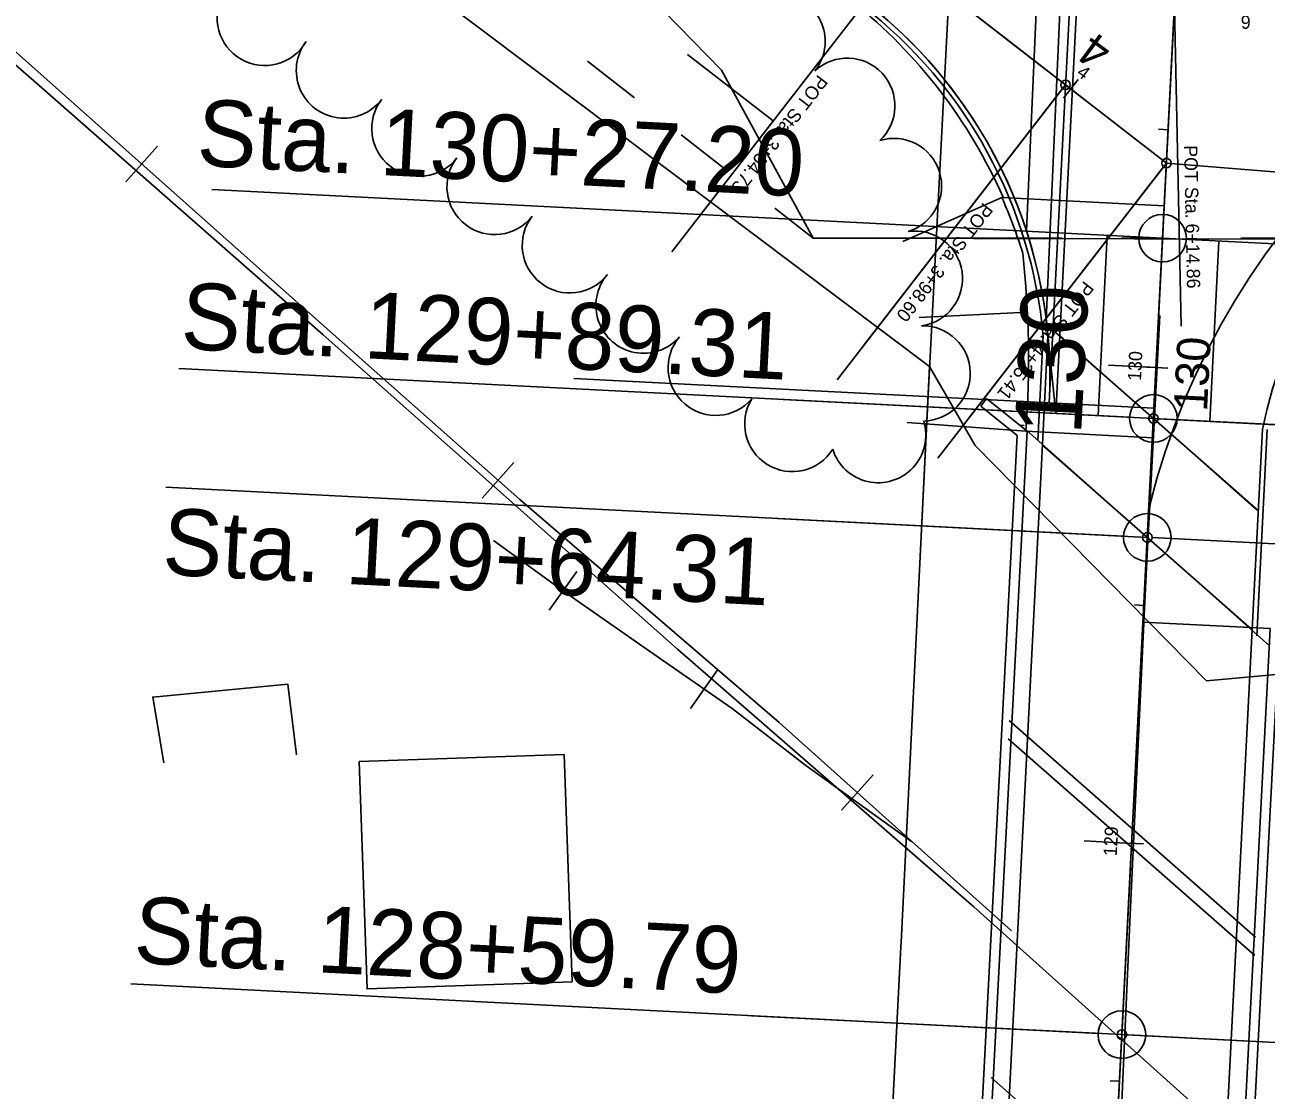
# Model space of a CAD drawing. Extents: x -25029 to 2274964, y -81170 to 687028.
# Drawn here: x -4248.3 to -3987.6, y -66880.9 to -66657.3 of the extents above; entities that cross this region are included whole.
import ezdxf

# ---------------------------------------------------------------- set-up
doc = ezdxf.new("R2010")
doc.units = 0
for name, color, linetype in [('81911BEA - RW_X_Fee_RW', 7, 'Continuous'), ('AP_X_Lights', 7, 'Continuous'), ('AP_X_Runway', 7, 'Continuous'), ('BD_X_Canopy', 7, 'Continuous'), ('BLDG', 7, 'Continuous'), ('BR_X_Rail_Object', 7, 'Continuous'), ('Default', 7, 'Continuous'), ('DIVISIONS', 7, 'Continuous'), ('DV_X_Corp_Line', 7, 'Continuous'), ('GE_X_CL_100', 7, 'Continuous'), ('GE_X_CL_20', 7, 'Continuous'), ('GE_X_CL_2000', 7, 'Continuous'), ('GK_Visualization', 7, 'Continuous'), ('MT_P_Lane_Line', 7, 'Continuous'), ('PM_P_CL_Double_Solid', 7, 'Continuous'), ('PM_P_Yield_Line', 7, 'Continuous'), ('PV_X_Curb', 7, 'Continuous'), ('PV_X_EOP', 7, 'Continuous'), ('RD_P_Gate', 7, 'Continuous'), ('RD_X_GR_Rt', 7, 'Continuous'), ('RD_X_RR_1', 7, 'Continuous'), ('RR', 7, 'Continuous'), ('TREES', 7, 'Continuous'), ('WALL', 7, 'Continuous')]:
    doc.layers.add(name, color=color, linetype=linetype)

msp = doc.modelspace()

# ---------------------------------------------------------------- linework, layer by layer
at = {"layer": '81911BEA - RW_X_Fee_RW'}
msp.add_line((-4044.67, -66469.26), (-4058.6, -66734.98), dxfattribs=at)
for points in [[(-4058.6, -66734.98), (-4060.47, -66773.14), (-4064.24, -66849.91), (-4064.29, -66850.79)], [(-4064.24, -66849.91), (-4064.29, -66850.79), (-4067.04, -66904.37), (-4080.46, -67165.32), (-4085.55, -67264.33), (-4100.93, -67563.4)]]:
    msp.add_lwpolyline(points, dxfattribs=at)
at = {"layer": 'AP_X_Lights'}
msp.add_line((-4009.95, -66718.26), (-4012.05, -66758.11), dxfattribs=at)
at = {"layer": 'AP_X_Runway'}
for p, q in [((-4031.74, -66738.84), (-4018.28, -66475.3)), ((-4009.34, -66702.04), (-3809.48, -66712.25)), ((-4033.42, -66722.48), (-4031.74, -66738.84)), ((-4011.27, -66739.88), (-3810.76, -66750.13)), ((-4017.88, -66869.24), (-3811.75, -66879.76))]:
    msp.add_line(p, q, dxfattribs=at)
msp.add_arc((-4133.02, -66731.48), 100, 5.1647, 52.2156, dxfattribs=at)
at = {"layer": 'BD_X_Canopy'}
for p, q in [((-4033.13, -66736.6), (-4009.6, -66275.87)), ((-4053.51, -67566.81), (-3994.85, -66418.3)), ((-4064.39, -66642.97), (-4112.39, -66704.89)), ((-4091.1, -66677.43), (-4109.14, -66663.45)), ((-4029.72, -66669.84), (-4077.72, -66731.77)), ((-4008.53, -66686.27), (-4056.53, -66748.19)), ((-4011.16, -66737.73), (-4133, -66731.5)), ((-4011.27, -66739.88), (-4089.04, -66735.91)), ((-4012.55, -66764.85), (-4090.32, -66760.88)), ((-4017.88, -66869.24), (-4095.65, -66865.26))]:
    msp.add_line(p, q, dxfattribs=at)
msp.add_arc((-4133, -66731.5), 100, 357.076, 52.2224, dxfattribs=at)
at = {"layer": 'BLDG'}
msp.add_lwpolyline([(-4135.03, -66810.42), (-4133.37, -66858.15), (-4176.4, -66859.64), (-4178.06, -66811.92)], close=True, dxfattribs=at)
at = {"layer": 'BR_X_Rail_Object'}
for p, q in [((-4047.54, -66737.29), (-4046.29, -66735.73)), ((-4039.85, -66743.49), (-4047.54, -66737.29)), ((-4037.8, -66742.57), (-4046.29, -66735.73)), ((-4048.44, -66946.28), (-4037.8, -66742.57)), ((-4037.8, -66742.47), (-3986.92, -66787.57)), ((-4050.34, -66944.22), (-4039.85, -66743.49)), ((-3986.73, -66784.01), (-3997.37, -66988.52)), ((-3984.84, -66786.07), (-3995.05, -66982.32))]:
    msp.add_line(p, q, dxfattribs=at)
at = {"layer": 'Default'}
for p, q in [((-4053.51, -67566.81), (-3987.63, -66276.99)), ((-4384.29, -66395.03), (-4008.53, -66686.26)), ((-4344.77, -66425.66), (-4008.53, -66686.26)), ((-4027.08, -66668.72), (-4030.15, -66672.68)), ((-4028.61, -66670.7), (-4028.61, -66670.7)), ((-4008.53, -66686.26), (-4008.53, -66686.26)), ((-4008.53, -66686.26), (-3651.55, -66715.33)), ((-4033.64, -66720.22), (-3989.23, -66759.26)), ((-4013.22, -66729.07), (-4008.23, -66729.32)), ((-4010.73, -66729.21), (-4010.73, -66729.21)), ((-4038.38, -66741.38), (-4039.38, -66741.32)), ((-4034.59, -66745.48), (-3990.51, -66784.23)), ((-4041.55, -66803.3), (-3989.8, -66848.79)), ((-4041.74, -66807.13), (-3989.99, -66852.61)), ((-4018.32, -66828.94), (-4013.33, -66829.19)), ((-4015.83, -66829.08), (-4015.83, -66829.08)), ((-4045.37, -66878.21), (-3993.62, -66923.69))]:
    msp.add_line(p, q, dxfattribs=at)
for points in [[(-4008.17, -66679.26), (-4005.88, -66634.32)], [(-4068.13, -66640.07), (-4032.57, -66667.64)], [(-4030.59, -66669.17), (-4026.64, -66672.23)], [(-4024.66, -66673.76), (-4008.53, -66686.26)], [(-4010.47, -66724.2), (-4008.17, -66679.26)], [(-4010.85, -66731.69), (-4010.6, -66726.7)], [(-4013.28, -66779.13), (-4010.98, -66734.19)], [(-4015.57, -66824.07), (-4013.28, -66779.13)], [(-4015.95, -66831.56), (-4015.7, -66826.57)], [(-4018.38, -66879), (-4016.08, -66834.06)], [(-4020.67, -66923.94), (-4018.38, -66879)]]:
    msp.add_lwpolyline(points, dxfattribs=at)
at = {"layer": 'DIVISIONS'}
for p, q in [((-4394.44, -66476.23), (-4058.29, -66729.01)), ((-4130.09, -66664.88), (-4120.26, -66672.6)), ((-4110.43, -66680.32), (-4100.6, -66688.04)), ((-4017.94, -66702.04), (-4009.34, -66702.04)), ((-3992.94, -66702.04), (-3980.44, -66702.04)), ((-4060.47, -66773.14), (-4058.3, -66728.98)), ((-4058.29, -66729.01), (-4048.69, -66745.55)), ((-4048.69, -66745.55), (-4000.13, -66794.95)), ((-4000.13, -66794.95), (-3961.59, -66791.43))]:
    msp.add_line(p, q, dxfattribs=at)
msp.add_lwpolyline([(-4090.77, -66695.75), (-4082.76, -66702.04), (-4030.44, -66702.04)], dxfattribs=at)
at = {"layer": 'DV_X_Corp_Line'}
for p, q in [((-4309.52, -66454.88), (-4101.95, -66666.75)), ((-4101.95, -66666.75), (-4082.76, -66702.04)), ((-4082.76, -66702.04), (-3919.61, -66702.4))]:
    msp.add_line(p, q, dxfattribs=at)
at = {"layer": 'GE_X_CL_100'}
for p, q in [((-4011.27, -66739.88), (-3997.69, -66474.06)), ((-4064.39, -66642.97), (-4029.72, -66669.84)), ((-4029.72, -66669.84), (-4008.53, -66686.27)), ((-4009.34, -66702.04), (-4209.04, -66691.84)), ((-4016.26, -66739.63), (-4215.97, -66729.43)), ((-4010.73, -66729.21), (-4020.71, -66728.7)), ((-4012.55, -66764.85), (-4011.27, -66739.88)), ((-4017.54, -66764.6), (-4218.69, -66754.32)), ((-4017.88, -66869.24), (-4012.55, -66764.85)), ((-4015.83, -66829.08), (-4025.81, -66828.57)), ((-4022.87, -66868.98), (-4226.04, -66858.6)), ((-4022.82, -66965.97), (-4017.88, -66869.24))]:
    msp.add_line(p, q, dxfattribs=at)
msp.add_lwpolyline([(-3984.29, -66700.81), (-3987.77, -66705.49), (-3991.06, -66710.3), (-3994.18, -66715.22), (-3997.11, -66720.26), (-3999.84, -66725.41), (-4002.38, -66730.66), (-4004.73, -66736), (-4006.87, -66741.42), (-4008.8, -66746.91), (-4010.53, -66752.48), (-4012.05, -66758.11)], dxfattribs=at)
for centre in [(-4009.34, -66702.04), (-4011.27, -66739.88), (-4012.55, -66764.85), (-4017.88, -66869.24)]:
    msp.add_circle(centre, 5, dxfattribs=at)
at = {"layer": 'GE_X_CL_20'}
for p, q in [((-4065.01, -66643.76), (-4106.66, -66697.49)), ((-4006.84, -66653.6), (-4005.44, -66720.51)), ((-4028.61, -66670.7), (-4027.39, -66669.12)), ((-4030.33, -66670.63), (-4072.09, -66724.51)), ((-4028.61, -66670.7), (-4029.84, -66672.28)), ((-4008.18, -66679.27), (-4010.17, -66679.17)), ((-4009.14, -66687.06), (-4050.17, -66739.99)), ((-4010.73, -66729.21), (-4012.72, -66729.11)), ((-4010.27, -66739.94), (-3939.56, -66743.55)), ((-4011.55, -66764.9), (-3940.82, -66768.52)), ((-4013.28, -66779.14), (-4015.27, -66779.04)), ((-4015.83, -66829.08), (-4017.82, -66828.98)), ((-4016.88, -66869.29), (-3945.35, -66872.94)), ((-4018.38, -66879.01), (-4020.38, -66878.91))]:
    msp.add_line(p, q, dxfattribs=at)
for centre in [(-4029.72, -66669.84), (-4008.53, -66686.27), (-4011.27, -66739.88), (-4012.55, -66764.85), (-4017.88, -66869.24)]:
    msp.add_circle(centre, 1, dxfattribs=at)
at = {"layer": 'GE_X_CL_2000'}
for points in [[(-4012.05, -66758.11), (-4012.52, -66766.98), (-4013.13, -66779.88)], [(-4013.13, -66779.88), (-4016.07, -66842.49), (-4020.3, -66936.62), (-4021.7, -66964.57), (-4023.91, -67006.53), (-4028.54, -67072.96), (-4032.5, -67158.45), (-4036.77, -67244.88), (-4039.82, -67307.81), (-4042.57, -67367.56), (-4046.26, -67421.58), (-4049.64, -67482.6), (-4051.75, -67539.48), (-4054.16, -67599.55), (-4055.96, -67650.71), (-4056.81, -67705.37), (-4056.4, -67751.12), (-4055.31, -67821.98), (-4053.28, -67876.95), (-4051.28, -67925.88), (-4048.02, -67968.46), (-4046.31, -67983.5), (-4044.52, -67998.52), (-4042.41, -68015.31)]]:
    msp.add_lwpolyline(points, dxfattribs=at)
at = {"layer": 'GK_Visualization'}
for p, q in [((-4011.27, -66739.88), (-3997.69, -66474.06)), ((-4064.39, -66642.97), (-4029.72, -66669.84)), ((-4029.79, -66669.91), (-4029.65, -66669.78)), ((-4029.79, -66669.78), (-4029.65, -66669.91)), ((-4029.72, -66669.84), (-4008.53, -66686.27)), ((-4008.6, -66686.33), (-4008.46, -66686.2)), ((-4008.6, -66686.2), (-4008.46, -66686.33)), ((-4012.55, -66764.85), (-4011.27, -66739.88)), ((-4011.34, -66739.95), (-4011.2, -66739.82)), ((-4011.34, -66739.82), (-4011.2, -66739.95)), ((-4017.88, -66869.24), (-4012.55, -66764.85)), ((-4012.61, -66764.92), (-4012.48, -66764.79)), ((-4012.61, -66764.79), (-4012.48, -66764.92)), ((-4022.82, -66965.97), (-4017.88, -66869.24)), ((-4017.95, -66869.3), (-4017.81, -66869.17)), ((-4017.95, -66869.17), (-4017.81, -66869.3))]:
    msp.add_line(p, q, dxfattribs=at)
at = {"layer": 'MT_P_Lane_Line'}
for p, q in [((-4022.9, -66739.29), (-4020.97, -66701.45)), ((-3999.43, -66740.49), (-3997.5, -66702.65))]:
    msp.add_line(p, q, dxfattribs=at)
at = {"layer": 'PM_P_CL_Double_Solid'}
msp.add_line((-4011.27, -66739.88), (-4009.34, -66702.04), dxfattribs=at)
at = {"layer": 'PM_P_Yield_Line'}
msp.add_line((-4035.72, -66650.46), (-4037.94, -66700.47), dxfattribs=at)
at = {"layer": 'PV_X_Curb'}
for p, q in [((-4035.54, -66744.48), (-4034.41, -66722.44)), ((-3989.57, -66785.55), (-3987.36, -66742.17))]:
    msp.add_line(p, q, dxfattribs=at)
msp.add_arc((-4133.01, -66731.49), 99, 5.1647, 52.2156, dxfattribs=at)
at = {"layer": 'PV_X_EOP'}
for p, q in [((-4033.76, -66719.2), (-4030.61, -66648.01)), ((-4034.65, -66746.75), (-4033.41, -66722.49)), ((-4030.88, -66722.51), (-3989.53, -66759.16)), ((-3990.57, -66785.5), (-3988.36, -66742.12)), ((-4044.79, -66945.32), (-4034.65, -66746.75)), ((-4000.71, -66984.07), (-3990.57, -66785.5))]:
    msp.add_line(p, q, dxfattribs=at)
for centre, start, end in [((-4133.01, -66731.49), 5.1647, 52.2156), ((-3890.39, -66762.18), 91.2017, 168.4297)]:
    msp.add_arc(centre, 100, start, end, dxfattribs=at)
at = {"layer": 'RD_P_Gate'}
for p, q in [((-4043.08, -66693.51), (-4063.92, -66702.71)), ((-4043.08, -66693.51), (-4043.08, -66693.51)), ((-4008.99, -66695.25), (-4043.08, -66693.51)), ((-4038.7, -66705.21), (-4038.7, -66705.21)), ((-4037.73, -66717.57), (-4060.49, -66718.67)), ((-4037.73, -66717.57), (-4037.73, -66717.57)), ((-4038.05, -66742.56), (-4063.01, -66740.72)), ((-4011.31, -66743.97), (-4038.05, -66742.56)), ((-4013.46, -66782.64), (-3986.73, -66784.01))]:
    msp.add_line(p, q, dxfattribs=at)
at = {"layer": 'RD_X_GR_Rt'}
for centre, radius, start, end in [((-4142.13, -66737.24), 108.52, 23.8231, 51.3485), ((-4142.13, -66737.24), 108.27, 17.1926, 23.8231), ((-4242.91, -66727.45), 205.42, 355.7836, 6.2217)]:
    msp.add_arc(centre, radius, start, end, dxfattribs=at)
at = {"layer": 'RD_X_RR_1'}
msp.add_line((-4048.95, -66842.4), (-3994.64, -66891.19), dxfattribs=at)
msp.add_lwpolyline([(-4380.95, -66550.04), (-4311.86, -66611.93), (-4245.26, -66669.98), (-4185.61, -66722.36), (-4111.23, -66788.33), (-4048.95, -66842.4)], dxfattribs=at)
at = {"layer": 'RR'}
for p, q in [((-4220.43, -66682.75), (-4227.07, -66690.23)), ((-4145.63, -66749.11), (-4152.26, -66756.6)), ((-4138.18, -66780.13), (-4132.33, -66772.02)), ((-4108.5, -66800.78), (-4102.78, -66792.57)), ((-4070.11, -66814.7), (-4076.78, -66822.15))]:
    msp.add_line(p, q, dxfattribs=at)
for points in [[(-4041.1, -66847.43), (-4089.85, -66803.72), (-4144.36, -66756.91), (-4193.35, -66713.51), (-4253.87, -66659.72), (-4315.09, -66606.92), (-4358.63, -66568.38)], [(-4149.88, -66765.52), (-4135.19, -66776.12), (-4117.08, -66788.71), (-4099.73, -66800.79), (-4084.28, -66812.73), (-4062.04, -66828.7)]]:
    msp.add_lwpolyline(points, dxfattribs=at)
at = {"layer": 'TREES'}
for centre, start, end in [((-4197.91, -66655.79), 150.2077, 330.2077), ((-4090.2, -66660.69), 321.3873, 141.3873), ((-4181.29, -66666.84), 142.6034, 322.6034), ((-4075.56, -66674.24), 312.9999, 132.9999), ((-4165.44, -66679.04), 142.2178, 322.2178), ((-4065.75, -66691.1), 287.3911, 107.3911), ((-4149.64, -66691.29), 142.2178, 322.2178), ((-4133.83, -66703.54), 142.2178, 322.2178), ((-4061.36, -66710.54), 278.0762, 98.0762), ((-4118.36, -66716.2), 139.1959, 319.1959), ((-4059.73, -66730.44), 271.285, 91.285), ((-4103.19, -66729.25), 139.4019, 319.4019), ((-4087.11, -66741.04), 148.1048, 328.1048), ((-4069.06, -66743.38), 197.1129, 17.1129)]:
    msp.add_arc(centre, 10, start, end, dxfattribs=at)
at = {"layer": 'WALL'}
msp.add_lwpolyline([(-4219.11, -66812.21), (-4221.43, -66798.37), (-4193.06, -66795.7), (-4191.23, -66810.52)], dxfattribs=at)

# ---------------------------------------------------------------- texts
at = {"layer": 'Default'}
for s, rotation, p in [('4', 143.4417, (-4019.43, -66661.6)), ('130', 87.076, (-4000.01, -66738.52))]:
    msp.add_text(s, height=7, rotation=rotation, dxfattribs=at).set_placement(p)
at = {"layer": 'DV_X_Corp_Line'}
msp.add_text('Sta. 130+27.20', height=14, rotation=357.076, dxfattribs=at).set_placement((-4212.36, -66686.8))
at = {"layer": 'GE_X_CL_100'}
for s, rotation, p in [('Sta. 129+89.31', 357.076, (-4215.71, -66725.26)), ('130', 87.076, (-4026.47, -66743.47)), ('Sta. 129+64.31', 357.076, (-4219.59, -66772.64)), ('Sta. 128+59.79', 357.076, (-4225.59, -66854.17))]:
    msp.add_text(s, height=14, rotation=rotation, dxfattribs=at).set_placement(p)
at = {"layer": 'GE_X_CL_20'}
for s, rotation, p in [('6', 181.2018, (-3990.86, -66655.26)), ('4', 322.2217, (-4027.59, -66667.69)), ('POT Sta. 3+54.73', 232.2217, (-4081.67, -66667.54)), ('POT Sta. 6+14.86', 271.2018, (-4004.84, -66682.56)), ('POT Sta. 3+98.60', 232.2217, (-4046.99, -66694.41)), ('POT Sta. 4+25.41', 232.2217, (-4025.8, -66710.84)), ('130', 87.076, (-4013.88, -66732.06)), ('129', 87.076, (-4018.97, -66831.83))]:
    msp.add_text(s, height=2.8, rotation=rotation, dxfattribs=at).set_placement(p)
at = {"layer": 'GK_Visualization'}
for s, p in [('91', (-4029.72, -66669.84)), ('92', (-4008.53, -66686.27)), ('120', (-4011.27, -66739.88)), ('119', (-4012.55, -66764.85)), ('118', (-4017.88, -66869.24))]:
    msp.add_text(s, height=0.14, dxfattribs=at).set_placement(p)

doc.saveas('drawing.dxf')
